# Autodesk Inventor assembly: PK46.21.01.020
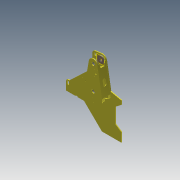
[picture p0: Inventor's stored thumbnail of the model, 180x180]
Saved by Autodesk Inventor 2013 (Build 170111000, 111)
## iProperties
Created: 2005-04
Part Number: PK46.21.01.020
Document SubType Name: Assembly
Designer: salex
Manufacturer: Standard
Standards Organization: Custom
Author: salex
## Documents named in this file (9)
- D:\FrontLoaderVault\Data\Assy, Chassis, Front\PK46.21.01.020.iam
- D:\FrontLoaderVault\Data\Assy, Chassis, Front\PK46.21.01.002.ipt
- D:\FrontLoaderVault\Data\Assy, Chassis, Front\PK46.21.01.033.ipt
- D:\FrontLoaderVault\Data\Assy, Chassis, Front\PK46.21.01.003.ipt
- D:\FrontLoaderVault\Data\Assy, Chassis, Front\PK46.21.01.004.ipt
- D:\FrontLoaderVault\Data\Assy, Chassis, Front\PK46.21.01.005.ipt
- D:\FrontLoaderVault\Data\Assy, Chassis, Front\PK46.80.00.015.ipt
- D:\FrontLoaderVault\Data\Assy, Chassis, Front\PK46.21.01.034.ipt
- D:\FrontLoaderVault\Data\Assy, Chassis, Front\PK46.21.01.001.ipt
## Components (10 placed, 8 different names)
1. PK46.21.01.002:1 — Mate:1, Insert:2, Mate:6, Insert:4, Mate:13, Mate:14, Mate:16, Angle:1, Mate:15, Insert:7
2. PK46.21.01.003:1 — Insert:6
3. PK46.21.01.003:2 — Insert:4
4. PK46.21.01.004:1 — Mate:6, Mate:10
5. PK46.21.01.005:1 — Mate:1, Mate:10, Flush:3, Mate:12
6. PK46.80.00.015:1 — Insert:2, Flush:2
7. PK46.80.00.015:2 — Insert:5
8. PK46.21.01.034:1 — Insert:7
9. PK46.21.01.001:1 — Insert:5, Insert:6, Flush:3, Mate:12, Mate:13, Mate:14
10. PK46.21.01.033:1 — Mate:16, Angle:1, Mate:15
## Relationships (16: Mate 8, Insert 5, Flush 2, Angle 1)
- Mate:1: PK46.21.01.002:1 ↔ PK46.21.01.005:1
- Insert:2: PK46.21.01.002:1 ↔ PK46.80.00.015:1
- Mate:6: PK46.21.01.002:1 ↔ PK46.21.01.004:1
- Insert:4: PK46.21.01.002:1 ↔ PK46.21.01.003:2
- Flush:2: PK46.80.00.015:1
- Mate:10: PK46.21.01.004:1 ↔ PK46.21.01.005:1
- Insert:5: PK46.80.00.015:2 ↔ PK46.21.01.001:1
- Insert:6: PK46.21.01.003:1 ↔ PK46.21.01.001:1
- Flush:3: PK46.21.01.005:1 ↔ PK46.21.01.001:1
- Mate:12: PK46.21.01.005:1 ↔ PK46.21.01.001:1
- Mate:13: PK46.21.01.002:1 ↔ PK46.21.01.001:1
- Mate:14: PK46.21.01.002:1 ↔ PK46.21.01.001:1
- Insert:7: PK46.21.01.002:1 ↔ PK46.21.01.034:1
- Mate:16: PK46.21.01.002:1 ↔ PK46.21.01.033:1
- Angle:1: PK46.21.01.002:1 ↔ PK46.21.01.033:1
- Mate:15: PK46.21.01.002:1 ↔ PK46.21.01.033:1
